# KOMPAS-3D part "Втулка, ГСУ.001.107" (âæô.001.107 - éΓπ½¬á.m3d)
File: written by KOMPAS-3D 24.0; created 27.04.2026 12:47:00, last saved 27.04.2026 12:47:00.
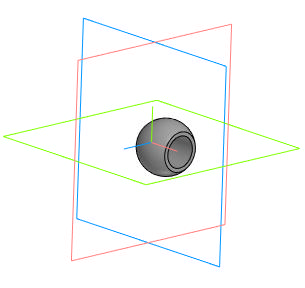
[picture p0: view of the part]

Document properties: Автор: User7; Полное имя файла: C:\Users\User7\Desktop\Двигатель мясорубки\ГСУ.001.107 - Втулка.m3d

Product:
- Part/product: Втулка  | designation ГСУ.001.107
    Масса: 0.00612

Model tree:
1. Эскиз:1
2. Элемент вращения:1
     Угол 1 = 360

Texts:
  ГСУ.001.107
